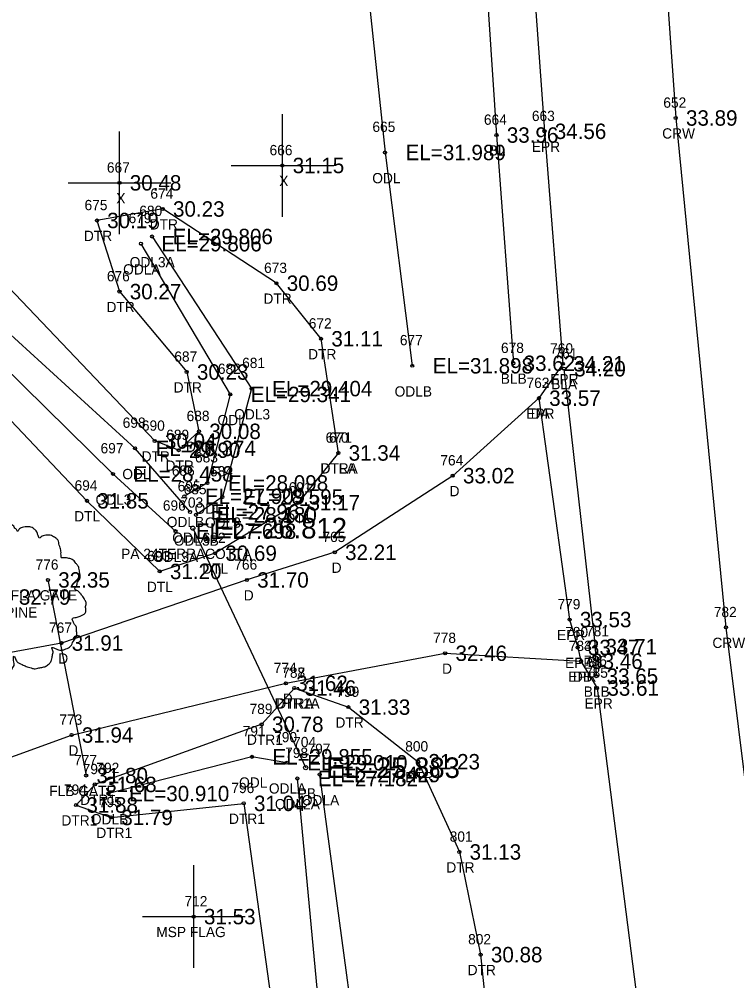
# Model space of a CAD drawing. Extents: x 2042211 to 2045853, y 303080 to 309569.
# Drawn here: x 2042782.9 to 2042852.8, y 307097.7 to 307191.3 of the extents above; entities that cross this region are included whole.
import ezdxf

# ---------------------------------------------------------------- set-up
doc = ezdxf.new("R2010")
doc.units = 0
for name, color, linetype in [('BR_500YR_SCOUR', 7, 'Continuous'), ('RD_DTM_BkLn1', 7, 'Continuous'), ('RD_DTM_BkLn_txCode', 7, 'Continuous'), ('RD_EX_DR_Pipe_txCode', 7, 'Continuous'), ('RD_EX_Driveway', 7, 'Continuous'), ('RD_EX_Driveway_txCode', 7, 'Continuous'), ('RD_EX_Fence_Other_txCode', 7, 'Continuous'), ('RD_EX_H2O', 7, 'Continuous'), ('RD_EX_H2O_txCode', 7, 'Continuous'), ('RD_EX_Misc', 7, 'Continuous'), ('RD_EX_Misc_txCode', 7, 'Continuous'), ('RD_EX_Road', 7, 'Continuous'), ('RD_EX_Road_txCode', 7, 'Continuous'), ('RD_EX_TX_Driveway_ELEV', 7, 'Continuous'), ('RD_EX_TX_Fence_Other_ELEV', 7, 'Continuous'), ('RD_EX_TX_H2O_ELEV', 7, 'Continuous'), ('RD_EX_TX_Misc_ELEV', 7, 'Continuous'), ('RD_EX_TX_Road_ELEV', 7, 'Continuous'), ('RD_EX_TX_VEG_ELEV', 7, 'Continuous'), ('RD_EX_VEG_txCode', 7, 'Continuous'), ('RD_HC_Survey_ELEV', 7, 'Continuous'), ('RD_HC_Survey_txCode', 7, 'Continuous'), ('RD_SMD_Locator', 7, 'Continuous'), ('RD_TX_Pipe_ElevEX', 7, 'Continuous')]:
    doc.layers.add(name, color=color, linetype=linetype)

msp = doc.modelspace()

# ---------------------------------------------------------------- linework, layer by layer
at = {"layer": 'BR_500YR_SCOUR'}
for p, q in [((2042799.852, 307141.729), (2042810.843, 307118.409)), ((2042785.745, 307136.69), (2042789.469, 307117.644))]:
    msp.add_line(p, q, dxfattribs=at)
for centre, radius in [((2042799.852, 307141.729), 0.2), ((2042785.745, 307136.69), 0.15), ((2042810.843, 307118.409), 0.2), ((2042789.469, 307117.644), 0.15)]:
    msp.add_circle(centre, radius, dxfattribs=at)
for points in [[(2042782.045, 307142.191), (2042781.746, 307142.216), (2042781.421, 307142.116), (2042781.171, 307142.016), (2042780.946, 307141.941), (2042780.721, 307141.841), (2042780.421, 307141.666), (2042780.196, 307141.466), (2042780.071, 307141.216), (2042780.021, 307140.991), (2042779.971, 307140.716), (2042779.971, 307140.541), (2042779.846, 307140.516), (2042779.696, 307140.541), (2042779.447, 307140.616), (2042779.197, 307140.616), (2042778.947, 307140.616), (2042778.597, 307140.591), (2042778.247, 307140.591), (2042777.972, 307140.541), (2042777.647, 307140.492), (2042777.273, 307140.367), (2042776.923, 307140.242), (2042776.623, 307139.992), (2042776.373, 307139.517), (2042776.248, 307139.167), (2042776.098, 307138.917), (2042776.248, 307138.467), (2042776.423, 307138.118), (2042776.448, 307137.918), (2042776.523, 307137.493), (2042776.623, 307137.268), (2042776.748, 307137.068), (2042776.673, 307137.043), (2042776.298, 307136.993), (2042775.998, 307136.893), (2042775.573, 307136.668), (2042775.348, 307136.443), (2042775.248, 307136.118), (2042775.223, 307135.769), (2042775.124, 307135.569), (2042775.049, 307135.294), (2042775.024, 307135.219), (2042774.974, 307134.894), (2042775.074, 307134.444), (2042775.099, 307134.094), (2042775.223, 307133.869), (2042775.373, 307133.695), (2042775.548, 307133.445), (2042775.948, 307133.22), (2042776.273, 307133.12), (2042776.473, 307133.095), (2042776.298, 307132.595), (2042776.248, 307132.245), (2042776.123, 307131.845), (2042776.123, 307131.77), (2042776.073, 307131.296), (2042776.223, 307130.971), (2042776.298, 307130.596), (2042776.473, 307130.371), (2042776.748, 307130.071), (2042777.073, 307129.846), (2042777.572, 307129.721), (2042777.972, 307129.746), (2042778.547, 307129.921), (2042778.797, 307129.996), (2042778.772, 307129.821), (2042778.797, 307129.446), (2042778.797, 307129.022), (2042778.947, 307128.697), (2042779.047, 307128.422), (2042779.197, 307128.172), (2042779.522, 307127.947), (2042779.921, 307127.872), (2042780.346, 307127.722), (2042780.796, 307127.647), (2042781.296, 307127.622), (2042781.896, 307127.772), (2042782.17, 307127.897), (2042782.27, 307128.072), (2042782.47, 307128.447), (2042782.42, 307128.672), (2042782.445, 307129.271), (2042782.545, 307129.096), (2042782.72, 307128.747), (2042783.22, 307128.447), (2042783.62, 307128.272), (2042784.095, 307128.122), (2042784.394, 307128.047), (2042784.869, 307128.122), (2042785.244, 307128.197), (2042785.619, 307128.322), (2042785.919, 307128.597), (2042786.094, 307128.872), (2042786.144, 307129.146), (2042786.219, 307129.521), (2042786.269, 307129.696)], [(2042786.269, 307129.696), (2042786.194, 307129.871), (2042786.144, 307130.121), (2042786.219, 307130.096), (2042786.394, 307130.046), (2042786.668, 307129.921), (2042786.893, 307129.846), (2042787.218, 307129.871), (2042787.493, 307129.971), (2042787.943, 307130.246), (2042788.218, 307130.721), (2042788.493, 307131.121), (2042788.568, 307131.445), (2042788.518, 307131.67), (2042788.493, 307132.17), (2042788.293, 307132.42), (2042788.243, 307132.545), (2042788.143, 307132.945), (2042788.218, 307132.995), (2042788.493, 307133.045), (2042788.867, 307133.17), (2042789.142, 307133.295), (2042789.367, 307133.47), (2042789.442, 307133.695), (2042789.417, 307134.094), (2042789.467, 307134.494), (2042789.392, 307134.644), (2042789.292, 307134.794), (2042789.217, 307134.994), (2042789.067, 307135.144), (2042788.967, 307135.294), (2042788.867, 307135.394), (2042788.743, 307135.544), (2042788.568, 307135.669), (2042788.418, 307135.719), (2042788.368, 307135.869), (2042788.518, 307136.068), (2042788.568, 307136.168), (2042788.593, 307136.393), (2042788.818, 307136.743), (2042788.867, 307137.143), (2042788.818, 307137.568), (2042788.768, 307137.843), (2042788.618, 307138.118), (2042788.418, 307138.367), (2042788.293, 307138.542), (2042788.118, 307138.667), (2042787.793, 307138.792), (2042787.543, 307138.842), (2042787.193, 307138.842), (2042786.993, 307138.892), (2042787.018, 307138.942), (2042787.018, 307139.092), (2042787.018, 307139.367), (2042786.943, 307139.817), (2042786.793, 307140.317), (2042786.793, 307140.342), (2042786.693, 307140.591), (2042786.469, 307140.791), (2042786.294, 307140.891), (2042786.094, 307141.016), (2042785.844, 307141.041), (2042785.544, 307141.041), (2042785.269, 307140.991), (2042785.069, 307140.891), (2042784.894, 307140.766), (2042784.819, 307140.916), (2042784.719, 307141.216), (2042784.669, 307141.366), (2042784.519, 307141.541), (2042784.295, 307141.741), (2042783.845, 307141.866), (2042783.22, 307141.791), (2042782.92, 307141.591), (2042782.77, 307141.416), (2042782.72, 307141.541), (2042782.52, 307141.741), (2042782.42, 307141.916), (2042782.245, 307142.041), (2042782.095, 307142.141), (2042781.995, 307142.191)]]:
    msp.add_spline(points, degree=3, dxfattribs=at)
at = {"layer": 'RD_DTM_BkLn1'}
for points in [[(2042823.154, 307329.29), (2042823.591, 307279.347), (2042826.127, 307229.983), (2042829.424, 307180.004), (2042831.063, 307157.785)], [(2042839.809, 307329.372), (2042840.927, 307280.457), (2042843.389, 307231.171), (2042846.871, 307181.663), (2042851.763, 307132.066), (2042857.831, 307083.356), (2042865.029, 307034.365), (2042873.56, 306985.673), (2042883.709, 306937.587), (2042895.325, 306889.274), (2042908.008, 306841.406), (2042921.81, 306793.882), (2042936.829, 306746.34), (2042953.049, 306699.555), (2042970.364, 306653.599), (2042989.255, 306607.343), (2043009.361, 306561.991), (2043030.441, 306517.387), (2043052.89, 306472.911), (2043076.304, 306429.265), (2043100.429, 306386.207)], [(2042835.989, 307157.254), (2042839.035, 307130.2), (2042839.142, 307127.322)]]:
    msp.add_lwpolyline(points, dxfattribs=at)
at = {"layer": 'RD_EX_Driveway'}
for points in [[(2042833.55, 307154.384), (2042825.159, 307146.837), (2042813.676, 307139.379), (2042805.118, 307136.689), (2042787.057, 307130.546), (2042752.791, 307124.242)], [(2042754.933, 307109.556), (2042788.047, 307121.589), (2042808.918, 307126.626), (2042824.427, 307129.552), (2042837.641, 307128.77)]]:
    msp.add_lwpolyline(points, dxfattribs=at)
at = {"layer": 'RD_EX_H2O'}
for points in [[(2042809.034, 307329.141), (2042809.101, 307278.692), (2042813.163, 307229.385), (2042818.569, 307178.306), (2042821.216, 307157.54)], [(2042814.027, 307149.05), (2042810.112, 307144.206), (2042802.017, 307139.291), (2042796.625, 307137.517), (2042789.542, 307144.391), (2042765.069, 307170.219), (2042764.169, 307170.659), (2042753.465, 307183.772), (2042731.919, 307203.607), (2042715.016, 307220.147), (2042682.706, 307253.516), (2042652.804, 307280.333), (2042645.058, 307288.416)], [(2042798.162, 307141.437), (2042792.071, 307147.012), (2042768.023, 307170.668), (2042763.43, 307175.3), (2042754.912, 307185.665), (2042734.729, 307206.069), (2042717.18, 307221.145), (2042685.329, 307255.34), (2042657.065, 307284.58)], [(2042814.027, 307149.05), (2042812.345, 307160.168), (2042807.995, 307165.577), (2042796.924, 307172.805), (2042790.514, 307171.687), (2042792.711, 307164.761), (2042799.253, 307156.934), (2042800.452, 307151.156), (2042798.465, 307149.319), (2042796.137, 307150.217), (2042774.771, 307172.667), (2042769.031, 307177.057), (2042766.927, 307183.712), (2042770.194, 307195.04), (2042774.132, 307209.863), (2042772.991, 307212.659), (2042769.772, 307209.877), (2042763.427, 307196.276), (2042761.186, 307187.089), (2042759.154, 307187.365), (2042738.043, 307209.089), (2042720.637, 307223.823), (2042688.551, 307257.732)], [(2042799.58, 307143.305), (2042794.228, 307149.499), (2042770.351, 307171.286), (2042764.65, 307176.624), (2042764.081, 307182.37), (2042767.479, 307195.816), (2042771.696, 307208.761)], [(2042795.887, 307170.125), (2042805.575, 307155.319), (2042802.726, 307144.771), (2042800.163, 307143.026)], [(2042794.799, 307169.425), (2042803.495, 307154.751), (2042801.269, 307146.129), (2042799.033, 307144.831)], [(2042809.741, 307126.164), (2042806.558, 307122.634), (2042790.31, 307116.781), (2042788.489, 307114.776), (2042791.888, 307113.566), (2042804.809, 307114.936), (2042810.254, 307075.927), (2042820.25, 307025.916), (2042830.402, 306977.214), (2042843.286, 306928.12), (2042852.907, 306878.242), (2042864.554, 306828.434), (2042879.232, 306781.717), (2042889.452, 306748.733), (2042886.162, 306741.984), (2042888.342, 306727.944), (2042896.131, 306676.354), (2042885.674, 306665.433), (2042857.251, 306612.72)], [(2042809.741, 307126.164), (2042815.006, 307124.307), (2042821.793, 307118.991), (2042825.803, 307110.204), (2042827.879, 307100.209), (2042830.079, 307078.706), (2042836.245, 307029.115), (2042845.477, 306980.043), (2042852.07, 306929.459), (2042864.584, 306881.255), (2042879.311, 306833.064), (2042893.367, 306784.782), (2042908.764, 306736.234), (2042928.775, 306689.39), (2042938.935, 306669.11)], [(2042808.991, 307118.887), (2042805.603, 307119.467), (2042791.641, 307115.891)], [(2042810.023, 307117.36), (2042813.866, 307076.179), (2042825.646, 307027.003), (2042835.988, 306978.447), (2042846.189, 306929.265), (2042857.498, 306879.973), (2042870.301, 306830.673), (2042885.373, 306782.676), (2042895.573, 306748.275), (2042892.025, 306740.631), (2042891.661, 306731.268), (2042905.953, 306680.583), (2042906.869, 306643.176), (2042864.966, 306605.633)], [(2042812.202, 307117.747), (2042817.664, 307076.987), (2042828.965, 307027.386), (2042840.42, 306978.95), (2042848.435, 306929.659), (2042859.837, 306880.358), (2042873.681, 306831.671), (2042888.543, 306783.43), (2042900.594, 306749.272), (2042902.903, 306733.666), (2042926.042, 306688.214), (2042936.455, 306668.372), (2042947.444, 306643.989), (2042966.182, 306597.912), (2042985.34, 306551.144), (2042987.611, 306538.586)]]:
    msp.add_lwpolyline(points, dxfattribs=at)
at = {"layer": 'RD_EX_Misc'}
for p, q in [((2042808.576, 307172.039), (2042808.576, 307182.039)), ((2042792.713, 307170.349), (2042792.713, 307180.349)), ((2042803.576, 307177.039), (2042813.576, 307177.039)), ((2042787.713, 307175.349), (2042797.713, 307175.349)), ((2042799.938, 307098.913), (2042799.938, 307108.913)), ((2042794.938, 307103.913), (2042804.938, 307103.913))]:
    msp.add_line(p, q, dxfattribs=at)
at = {"layer": 'RD_EX_Road'}
msp.add_lwpolyline([(2042826.878, 307329.287), (2042828.013, 307279.816), (2042830.497, 307230.241), (2042834.094, 307180.367), (2042835.887, 307157.733), (2042833.55, 307154.384), (2042836.54, 307132.831), (2042837.327, 307130.114), (2042837.641, 307128.77), (2042839.219, 307126.163), (2042844.982, 307081.334), (2042852.857, 307032.13), (2042861.739, 306982.988), (2042871.664, 306934.616), (2042883.382, 306885.882), (2042895.938, 306837.564), (2042909.761, 306789.886)], dxfattribs=at)
at = {"layer": 'RD_SMD_Locator'}
for centre in [(2042846.871, 307181.663), (2042829.424, 307180.004), (2042834.094, 307180.367), (2042818.569, 307178.306), (2042808.576, 307177.039), (2042792.713, 307175.349), (2042796.924, 307172.805), (2042790.514, 307171.687), (2042795.887, 307170.125), (2042794.799, 307169.425), (2042807.995, 307165.577), (2042792.711, 307164.761), (2042812.345, 307160.168), (2042821.216, 307157.54), (2042831.063, 307157.785), (2042835.887, 307157.733), (2042799.253, 307156.934), (2042835.989, 307157.254), (2042803.495, 307154.751), (2042805.575, 307155.319), (2042833.55, 307154.384), (2042833.55, 307154.384), (2042800.452, 307151.156), (2042796.137, 307150.217), (2042794.228, 307149.499), (2042798.465, 307149.319), (2042814.027, 307149.05), (2042814.027, 307149.05), (2042792.071, 307147.012), (2042801.269, 307146.129), (2042825.159, 307146.837), (2042789.542, 307144.391), (2042799.033, 307144.831), (2042802.726, 307144.771), (2042810.112, 307144.206), (2042799.58, 307143.305), (2042800.163, 307143.026), (2042798.162, 307141.437), (2042802.017, 307139.291), (2042813.676, 307139.379), (2042796.625, 307137.517), (2042805.118, 307136.689), (2042836.54, 307132.831), (2042851.763, 307132.066), (2042787.057, 307130.546), (2042839.035, 307130.2), (2042824.427, 307129.552), (2042837.327, 307130.114), (2042837.641, 307128.77), (2042837.641, 307128.77), (2042808.918, 307126.626), (2042839.142, 307127.322), (2042809.741, 307126.164), (2042809.741, 307126.164), (2042839.219, 307126.163), (2042815.006, 307124.307), (2042806.558, 307122.634), (2042788.047, 307121.589), (2042805.603, 307119.467), (2042821.793, 307118.991), (2042808.991, 307118.887), (2042810.023, 307117.36), (2042812.202, 307117.747), (2042790.31, 307116.781), (2042791.641, 307115.891), (2042788.489, 307114.776), (2042804.809, 307114.936), (2042791.888, 307113.566), (2042825.803, 307110.204), (2042799.938, 307103.913), (2042827.879, 307100.209)]:
    msp.add_circle(centre, 0.15, dxfattribs=at)

# ---------------------------------------------------------------- texts
at = {"layer": 'RD_DTM_BkLn_txCode'}
for s, p in [('664', (2042828.196, 307181.004)), ('BL', (2042828.668, 307178.004)), ('678', (2042829.858, 307158.785)), ('761', (2042835.068, 307158.254)), ('BLB', (2042829.835, 307155.785)), ('BLA', (2042834.745, 307155.254)), ('781', (2042838.137, 307131.2)), ('786', (2042837.938, 307128.322)), ('BL', (2042838.279, 307128.2)), ('BLB', (2042837.914, 307125.322))]:
    msp.add_text(s, height=1, dxfattribs=at).set_placement(p)
at = {"layer": 'RD_EX_DR_Pipe_txCode'}
for s, p in [('703', (2042798.631, 307143.729)), ('PA 24TERRACOTTA', (2042792.875, 307138.729)), ('704', (2042809.623, 307120.409)), ('PB', (2042810.064, 307115.409))]:
    msp.add_text(s, height=1, dxfattribs=at).set_placement(p)
at = {"layer": 'RD_EX_Driveway_txCode'}
for s, p in [('763', (2042832.346, 307155.384)), ('DA', (2042832.755, 307152.384)), ('764', (2042823.954, 307147.837)), ('D', (2042824.852, 307144.837)), ('765', (2042812.471, 307140.379)), ('766', (2042803.89, 307137.689)), ('D', (2042813.369, 307137.379)), ('D', (2042804.811, 307134.689)), ('767', (2042785.852, 307131.546)), ('778', (2042823.246, 307130.552)), ('784', (2042836.46, 307129.77)), ('D', (2042786.75, 307128.546)), ('774', (2042807.736, 307127.626)), ('D', (2042824.12, 307127.552)), ('DB', (2042836.862, 307126.77)), ('D', (2042808.61, 307124.626)), ('773', (2042786.865, 307122.589)), ('D', (2042787.74, 307119.589))]:
    msp.add_text(s, height=1, dxfattribs=at).set_placement(p)
at = {"layer": 'RD_EX_Fence_Other_txCode'}
for s, p in [('776', (2042784.54, 307137.69)), ('FLA GATE', (2042782.119, 307134.69)), ('777', (2042788.287, 307118.644)), ('FLB GATE', (2042785.874, 307115.644))]:
    msp.add_text(s, height=1, dxfattribs=at).set_placement(p)
at = {"layer": 'RD_EX_H2O_txCode'}
for s, p in [('665', (2042817.341, 307180.306)), ('ODL', (2042817.325, 307175.306)), ('674', (2042795.719, 307173.805)), ('675', (2042789.309, 307172.687)), ('679', (2042793.595, 307171.425)), ('680', (2042794.643, 307172.125)), ('DTR', (2042795.656, 307170.805)), ('DTR', (2042789.246, 307169.687)), ('ODL3A', (2042793.705, 307167.125)), ('ODLA', (2042793.067, 307166.425)), ('673', (2042806.79, 307166.577)), ('676', (2042791.483, 307165.761)), ('DTR', (2042806.727, 307163.577)), ('DTR', (2042791.443, 307162.761)), ('672', (2042811.141, 307161.168)), ('677', (2042820.011, 307159.54)), ('687', (2042798.048, 307157.934)), ('DTR', (2042811.078, 307158.168)), ('682', (2042802.29, 307156.751)), ('681', (2042804.654, 307157.319)), ('DTR', (2042797.985, 307154.934)), ('ODLB', (2042819.5, 307154.54)), ('688', (2042799.247, 307152.156)), ('ODL', (2042802.251, 307151.751)), ('ODL3', (2042803.882, 307152.319)), ('698', (2042793.023, 307151.499)), ('690', (2042794.893, 307151.217)), ('689', (2042797.261, 307150.319)), ('670', (2042812.783, 307150.05)), ('671', (2042813.105, 307150.05)), ('697', (2042790.866, 307149.012)), ('DTR', (2042799.184, 307149.156)), ('DTR', (2042794.869, 307148.217)), ('683', (2042800.065, 307148.129)), ('DTR', (2042797.198, 307147.319)), ('ODL', (2042792.984, 307146.499)), ('686', (2042797.805, 307146.831)), ('684', (2042801.521, 307146.771)), ('DTRA', (2042812.271, 307147.05)), ('DTLA', (2042812.294, 307147.05)), ('694', (2042788.337, 307145.391)), ('695', (2042798.375, 307145.305)), ('691', (2042809.19, 307145.206)), ('685', (2042798.958, 307145.026)), ('ODL3', (2042790.378, 307144.012)), ('696', (2042796.934, 307143.437)), ('ODL', (2042800.025, 307143.129)), ('DTL', (2042788.298, 307142.391)), ('ODLB', (2042797.317, 307141.831)), ('ODL3', (2042801.033, 307141.771)), ('DTL', (2042808.867, 307142.206)), ('ODLA', (2042797.848, 307140.305)), ('ODL3B', (2042797.998, 307140.026)), ('692', (2042800.812, 307140.291)), ('693', (2042795.42, 307138.517)), ('ODL3A', (2042795.981, 307138.437)), ('DTL', (2042800.773, 307137.291)), ('DTL', (2042795.381, 307135.517)), ('787', (2042808.56, 307127.164)), ('788', (2042808.56, 307127.164)), ('799', (2042813.825, 307125.307)), ('DTR1A', (2042807.82, 307124.164)), ('DTRA', (2042807.985, 307124.164)), ('789', (2042805.377, 307123.634)), ('DTR', (2042813.739, 307122.307)), ('791', (2042804.706, 307121.467)), ('790', (2042807.77, 307120.887)), ('DTR1', (2042805.125, 307120.634)), ('800', (2042820.533, 307119.991)), ('798', (2042808.842, 307119.36)), ('797', (2042811.02, 307119.747)), ('793', (2042789.128, 307117.781)), ('792', (2042790.46, 307117.891)), ('ODL', (2042804.359, 307116.467)), ('DTR', (2042820.525, 307116.991)), ('794', (2042787.308, 307115.776)), ('796', (2042803.604, 307115.936)), ('ODLA', (2042807.258, 307115.887)), ('DTR1', (2042788.876, 307114.781)), ('795', (2042790.707, 307114.566)), ('ODL2A', (2042807.842, 307114.36)), ('ODLA', (2042810.469, 307114.747)), ('DTR1', (2042787.056, 307112.776)), ('ODLB', (2042789.925, 307112.891)), ('DTR1', (2042803.376, 307112.936)), ('DTR1', (2042790.455, 307111.566)), ('801', (2042824.866, 307111.204)), ('DTR', (2042824.535, 307108.204)), ('802', (2042826.659, 307101.209)), ('DTR', (2042826.611, 307098.209))]:
    msp.add_text(s, height=1, dxfattribs=at).set_placement(p)
at = {"layer": 'RD_EX_Misc_txCode'}
for s, p in [('666', (2042807.324, 307178.039)), ('667', (2042791.485, 307176.349)), ('X', (2042808.261, 307175.039)), ('X', (2042792.398, 307173.349)), ('712', (2042799.04, 307104.913)), ('MSP FLAG', (2042796.292, 307101.913))]:
    msp.add_text(s, height=1, dxfattribs=at).set_placement(p)
at = {"layer": 'RD_EX_Road_txCode'}
for s, p in [('663', (2042832.866, 307181.367)), ('EPR', (2042832.866, 307178.367)), ('760', (2042834.643, 307158.733)), ('EPR', (2042834.658, 307155.733)), ('762', (2042832.346, 307155.384)), ('EPR', (2042832.322, 307152.384)), ('779', (2042835.359, 307133.831)), ('EPR', (2042835.312, 307130.831)), ('780', (2042836.107, 307131.114)), ('783', (2042836.46, 307129.77)), ('EPR', (2042836.099, 307128.114)), ('EPR', (2042836.413, 307126.77)), ('785', (2042838.038, 307127.163)), ('EPR', (2042837.991, 307124.163))]:
    msp.add_text(s, height=1, dxfattribs=at).set_placement(p)
at = {"layer": 'RD_EX_TX_Driveway_ELEV'}
for s, p in [('33.57', (2042834.55, 307153.634)), ('33.02', (2042826.159, 307146.087)), ('32.21', (2042814.676, 307138.629)), ('31.70', (2042806.118, 307135.939)), ('31.91', (2042788.057, 307129.796)), ('32.46', (2042825.427, 307128.802)), ('33.46', (2042838.641, 307128.02)), ('31.62', (2042809.918, 307125.876)), ('31.94', (2042789.047, 307120.839))]:
    msp.add_text(s, height=1.5, dxfattribs=at).set_placement(p)
at = {"layer": 'RD_EX_TX_Fence_Other_ELEV'}
for s, p in [('32.35', (2042786.745, 307135.94)), ('31.80', (2042790.469, 307116.894))]:
    msp.add_text(s, height=1.5, dxfattribs=at).set_placement(p)
at = {"layer": 'RD_EX_TX_H2O_ELEV'}
for s, p in [('EL=31.989', (2042820.569, 307177.556)), ('30.23', (2042797.924, 307172.055)), ('30.19', (2042791.514, 307170.937)), ('EL=29.806', (2042797.887, 307169.375)), ('EL=29.806', (2042796.799, 307168.675)), ('30.69', (2042808.995, 307164.827)), ('30.27', (2042793.711, 307164.011)), ('31.11', (2042813.345, 307159.418)), ('30.23', (2042800.253, 307156.184)), ('EL=31.898', (2042823.216, 307156.79)), ('EL=29.404', (2042807.575, 307154.569)), ('EL=29.341', (2042805.495, 307154.001)), ('30.08', (2042801.452, 307150.406)), ('30.04', (2042797.137, 307149.467)), ('EL=28.374', (2042796.228, 307148.749)), ('29.90', (2042799.465, 307148.569)), ('31.34', (2042815.027, 307148.3)), ('31.34', (2042815.027, 307148.3)), ('EL=28.458', (2042794.071, 307146.262)), ('EL=28.098', (2042803.269, 307145.379)), ('EL=27.909', (2042801.033, 307144.081)), ('EL=28.595', (2042804.726, 307144.021)), ('31.85', (2042790.542, 307143.641)), ('31.17', (2042811.112, 307143.456)), ('EL=27.967', (2042801.58, 307142.555)), ('EL=28.180', (2042802.163, 307142.276)), ('EL=27.698', (2042800.162, 307140.687)), ('30.69', (2042803.017, 307138.541)), ('31.20', (2042797.625, 307136.767)), ('31.46', (2042810.741, 307125.414)), ('31.46', (2042810.741, 307125.414)), ('31.33', (2042816.006, 307123.557)), ('30.78', (2042807.558, 307121.884)), ('EL=29.855', (2042807.603, 307118.717)), ('EL=29.010', (2042810.991, 307118.137)), ('31.23', (2042822.793, 307118.241)), ('EL=27.182', (2042812.023, 307116.61)), ('EL=27.429', (2042814.202, 307116.997)), ('31.68', (2042791.31, 307116.031)), ('EL=30.910', (2042793.641, 307115.141)), ('31.88', (2042789.489, 307114.026)), ('31.04', (2042805.809, 307114.186)), ('31.79', (2042792.888, 307112.816)), ('31.13', (2042826.803, 307109.454)), ('30.88', (2042828.879, 307099.459))]:
    msp.add_text(s, height=1.5, dxfattribs=at).set_placement(p)
at = {"layer": 'RD_EX_TX_Misc_ELEV'}
for s, p in [('33.96', (2042830.424, 307179.254)), ('31.15', (2042809.576, 307176.289)), ('30.48', (2042793.713, 307174.599)), ('33.62', (2042832.063, 307157.035)), ('34.20', (2042836.989, 307156.504)), ('33.71', (2042840.035, 307129.45)), ('33.65', (2042840.142, 307126.572)), ('31.53', (2042800.938, 307103.163))]:
    msp.add_text(s, height=1.5, dxfattribs=at).set_placement(p)
at = {"layer": 'RD_EX_TX_Road_ELEV'}
for s, p in [('34.56', (2042835.094, 307179.617)), ('34.21', (2042836.887, 307156.983)), ('33.57', (2042834.55, 307153.634)), ('33.53', (2042837.54, 307132.081)), ('33.47', (2042838.327, 307129.364)), ('33.46', (2042838.641, 307128.02)), ('33.61', (2042840.219, 307125.413))]:
    msp.add_text(s, height=1.5, dxfattribs=at).set_placement(p)
at = {"layer": 'RD_EX_TX_VEG_ELEV'}
msp.add_text('32.79', height=1.5, dxfattribs=at).set_placement((2042782.914, 307134.274))
at = {"layer": 'RD_EX_VEG_txCode'}
msp.add_text('T 12PINE', height=1, dxfattribs=at).set_placement((2042778.91, 307133.024))
at = {"layer": 'RD_HC_Survey_ELEV'}
msp.add_text('33.89', height=1.5, dxfattribs=at).set_placement((2042847.871, 307180.913))
at = {"layer": 'RD_HC_Survey_txCode'}
for s, p in [('652', (2042845.666, 307182.663)), ('CRW', (2042845.556, 307179.663)), ('782', (2042850.582, 307133.066)), ('CRW', (2042850.448, 307130.066))]:
    msp.add_text(s, height=1, dxfattribs=at).set_placement(p)
at = {"layer": 'RD_TX_Pipe_ElevEX'}
for s, p in [('EL=26.812', (2042801.852, 307140.729)), ('EL=25.883', (2042812.843, 307117.409))]:
    msp.add_text(s, height=2, dxfattribs=at).set_placement(p)

doc.saveas('drawing.dxf')
